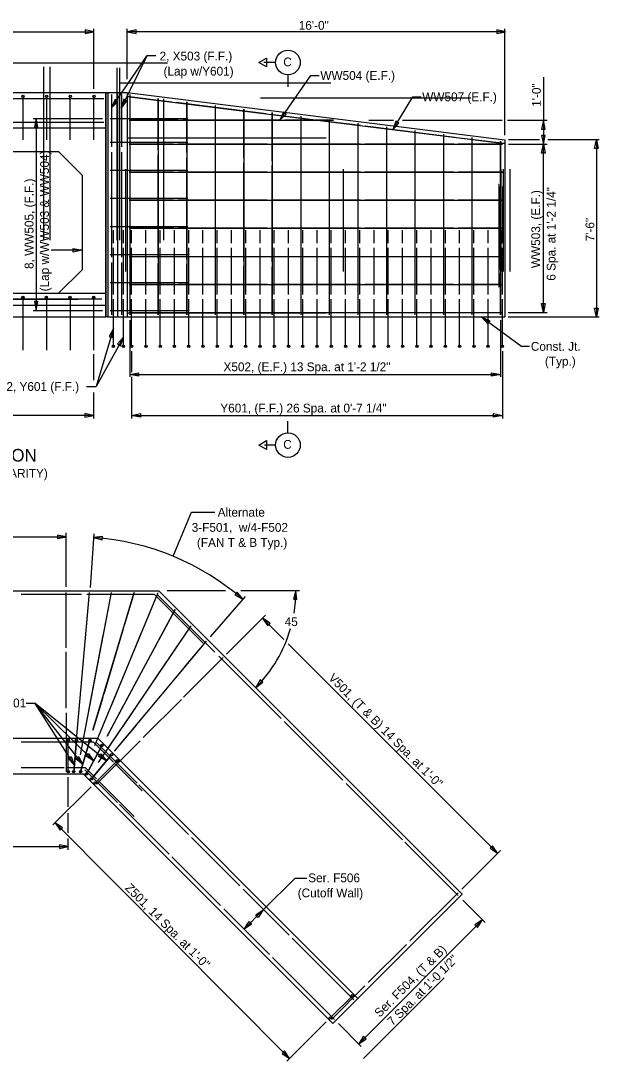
# Model space of a CAD drawing. Extents: x -1609 to 1184, y -412 to 394.
# Drawn here: x 695.6 to 720.11, y 231.37 to 275.43 of the extents above; entities that cross this region are included whole.
import ezdxf

# ---------------------------------------------------------------- set-up
doc = ezdxf.new("R2010")
doc.units = 0
for name, color, linetype in [('DR_P_Culvert', 7, 'Continuous'), ('DR_P_Headwall', 7, 'Continuous'), ('GE_P_CL_10', 7, 'Continuous'), ('ST_Details', 7, 'Continuous'), ('ST_Text', 7, 'Continuous')]:
    doc.layers.add(name, color=color, linetype=linetype)

msp = doc.modelspace()

# ---------------------------------------------------------------- linework, layer by layer
at = {"layer": 'DR_P_Culvert'}
for p, q in [((692.897, 273.646), (701.812, 273.646)), ((699.817, 272.805), (708.733, 272.805)), ((685.284, 272.144), (699.117, 272.144)), ((695.7, 270.391), (695.7, 272.227)), ((696.7, 270.391), (696.7, 272.227)), ((697.7, 270.391), (697.7, 272.227)), ((698.7, 270.391), (698.7, 272.227)), ((705.758, 272.169), (714.674, 272.169)), ((685.284, 271.141), (699.117, 271.141)), ((685.2, 270.891), (699.2, 270.891)), ((699.2, 270.891), (699.2, 262.894)), ((687.2, 269.891), (697.2, 269.891)), ((697.2, 269.891), (698.2, 268.891)), ((698.2, 268.891), (698.2, 264.891)), ((697.2, 263.891), (698.2, 264.891)), ((686.367, 263.641), (698.034, 263.641)), ((699.034, 263.641), (695.256, 263.641)), ((695.69, 263.724), (695.69, 261.477)), ((695.69, 263.724), (695.69, 261.477)), ((696.69, 263.724), (696.69, 261.477)), ((696.69, 263.724), (696.69, 261.477)), ((697.69, 263.724), (697.69, 261.477)), ((697.69, 263.724), (697.69, 261.477)), ((698.69, 263.724), (698.69, 261.477)), ((698.69, 263.724), (698.69, 261.477)), ((685.2, 262.894), (699.2, 262.894))]:
    msp.add_line(p, q, dxfattribs=at)
msp.add_lwpolyline([(699.2, 272.394), (699.285, 272.394), (699.285, 262.894), (699.2, 262.894)], close=True, dxfattribs=at)
for points in [[(694.012, 272.144), (697.306, 272.144)], [(697.47, 272.144), (699.117, 272.144)], [(694.012, 271.141), (697.306, 271.141)], [(697.47, 271.141), (699.117, 271.141)]]:
    msp.add_lwpolyline(points, dxfattribs=at)
at = {"layer": 'DR_P_Headwall'}
for p, q in [((685.2, 272.394), (699.2, 272.394)), ((699.2, 272.394), (699.2, 270.891)), ((699.285, 272.394), (699.285, 262.894)), ((699.285, 272.394), (700.113, 272.394)), ((699.699, 272.394), (699.699, 262.894)), ((700.113, 272.394), (716.112, 270.394)), ((700.113, 272.394), (700.113, 262.894)), ((716.112, 270.394), (716.112, 262.894)), ((687.2, 263.891), (697.2, 263.891)), ((697.2, 263.891), (699.2, 263.891)), ((699.2, 263.891), (699.2, 262.894)), ((685.2, 263.394), (699.2, 263.394)), ((685.2, 262.894), (698.2, 262.894)), ((677.116, 251.299), (701.457, 251.299)), ((714.308, 238.448), (701.457, 251.299)), ((677.116, 245.049), (698.868, 245.049)), ((709.889, 234.028), (698.868, 245.049)), ((677.116, 243.549), (698.247, 243.549)), ((708.829, 232.968), (698.247, 243.549)), ((714.308, 238.448), (708.829, 232.968))]:
    msp.add_line(p, q, dxfattribs=at)
for points in [[(699.446, 272.31), (699.446, 270.088)], [(699.869, 272.31), (699.869, 270.088)], [(699.446, 269.866), (699.446, 265.421)], [(699.869, 269.866), (699.869, 265.421)], [(699.446, 265.199), (699.446, 262.977)], [(699.869, 265.199), (699.869, 262.977)]]:
    msp.add_lwpolyline(points, dxfattribs=at)
at = {"layer": 'ST_Details'}
for p, q in [((696.565, 273.477), (696.565, 266.144)), ((696.828, 273.477), (696.828, 266.144)), ((699.676, 273.443), (699.676, 266.144)), ((699.791, 273.443), (699.791, 266.144)), ((700.217, 272.31), (700.217, 262.977)), ((700.092, 272.228), (716.091, 270.228)), ((701.425, 272.146), (701.425, 262.977)), ((701.644, 272.119), (701.644, 266.144)), ((702.634, 271.995), (702.634, 262.977)), ((703.842, 271.844), (703.842, 262.977)), ((705.05, 271.693), (705.05, 262.977)), ((706.259, 271.542), (706.259, 262.977)), ((707.467, 271.391), (707.467, 262.977)), ((699.388, 271.3), (702.685, 271.3)), ((700.196, 271.216), (708.859, 271.216)), ((708.675, 271.24), (708.675, 262.977)), ((709.884, 271.089), (709.884, 262.977)), ((711.092, 270.938), (711.092, 262.977)), ((712.3, 270.786), (712.3, 262.977)), ((713.509, 270.635), (713.509, 262.977)), ((699.388, 270.289), (702.685, 270.289)), ((700.123, 270.477), (708.539, 270.477)), ((700.196, 270.205), (716.019, 270.205)), ((714.717, 270.484), (714.717, 262.977)), ((715.925, 270.333), (715.925, 262.977)), ((699.388, 269.101), (702.685, 269.101)), ((700.043, 269.144), (700.043, 264.811)), ((700.196, 269.018), (716.019, 269.018)), ((709.262, 269.144), (709.262, 264.811)), ((715.936, 269.144), (715.936, 264.811)), ((716.036, 269.144), (716.036, 264.811)), ((716.316, 269.144), (716.316, 264.811)), ((715.853, 268.531), (715.853, 264.144)), ((716.009, 268.413), (716.009, 266.443)), ((699.388, 267.914), (702.685, 267.914)), ((700.196, 267.83), (716.019, 267.83)), ((699.388, 266.726), (702.685, 266.726)), ((699.529, 266.011), (699.529, 266.561)), ((699.952, 266.011), (699.952, 266.561)), ((700.196, 266.643), (716.019, 266.643)), ((700.3, 266.01), (700.3, 266.561)), ((700.904, 266.01), (700.904, 266.561)), ((701.509, 266.01), (701.509, 266.561)), ((702.113, 266.01), (702.113, 266.561)), ((702.717, 266.01), (702.717, 266.561)), ((703.321, 266.01), (703.321, 266.561)), ((703.925, 266.01), (703.925, 266.561)), ((704.529, 266.01), (704.529, 266.561)), ((705.134, 266.01), (705.134, 266.561)), ((705.738, 266.01), (705.738, 266.561)), ((706.342, 266.01), (706.342, 266.561)), ((706.946, 266.01), (706.946, 266.561)), ((707.55, 266.01), (707.55, 266.561)), ((708.154, 266.01), (708.154, 266.561)), ((708.759, 266.01), (708.759, 266.561)), ((709.363, 266.01), (709.363, 266.561)), ((709.967, 266.01), (709.967, 266.561)), ((710.571, 266.01), (710.571, 266.561)), ((711.175, 266.01), (711.175, 266.561)), ((711.779, 266.01), (711.779, 266.561)), ((712.384, 266.01), (712.384, 266.561)), ((712.988, 266.01), (712.988, 266.561)), ((713.592, 266.01), (713.592, 266.561)), ((714.196, 266.01), (714.196, 266.561)), ((714.8, 266.01), (714.8, 266.561)), ((715.404, 266.01), (715.404, 266.561)), ((716.009, 266.01), (716.009, 266.561)), ((699.529, 263.844), (699.529, 265.811)), ((699.952, 263.844), (699.952, 265.811)), ((700.3, 263.844), (700.3, 265.81)), ((700.904, 263.844), (700.904, 265.81)), ((701.509, 263.844), (701.509, 265.81)), ((702.113, 263.844), (702.113, 265.81)), ((702.717, 263.844), (702.717, 265.81)), ((703.321, 263.844), (703.321, 265.81)), ((703.925, 263.844), (703.925, 265.81)), ((704.529, 263.844), (704.529, 265.81)), ((705.134, 263.844), (705.134, 265.81)), ((705.738, 263.844), (705.738, 265.81)), ((706.342, 263.844), (706.342, 265.81)), ((706.946, 263.844), (706.946, 265.81)), ((707.55, 263.844), (707.55, 265.81)), ((708.154, 263.844), (708.154, 265.81)), ((708.759, 263.844), (708.759, 265.81)), ((709.363, 263.844), (709.363, 265.81)), ((709.967, 263.844), (709.967, 265.81)), ((710.571, 263.844), (710.571, 265.81)), ((711.175, 263.844), (711.175, 265.81)), ((711.779, 263.844), (711.779, 265.81)), ((712.384, 263.844), (712.384, 265.81)), ((712.988, 263.844), (712.988, 265.81)), ((713.592, 263.844), (713.592, 265.81)), ((714.196, 263.844), (714.196, 265.81)), ((714.8, 263.844), (714.8, 265.81)), ((715.404, 263.844), (715.404, 265.81)), ((716.009, 263.844), (716.009, 265.81)), ((699.388, 265.539), (702.685, 265.539)), ((700.196, 265.455), (716.019, 265.455)), ((699.388, 264.351), (702.685, 264.351)), ((700.196, 264.268), (716.019, 264.268)), ((699.388, 263.164), (702.685, 263.164)), ((700.123, 263.06), (708.539, 263.06)), ((700.196, 263.08), (716.019, 263.08)), ((699.285, 262.894), (716.112, 262.894)), ((697.532, 248.876), (697.532, 251.216)), ((701.27, 251.132), (698.396, 251.132)), ((703.332, 249.07), (701.27, 251.132)), ((703.827, 248.693), (701.388, 251.132)), ((697.532, 246.327), (697.532, 248.716)), ((706.639, 245.881), (703.989, 248.531)), ((702.502, 246.792), (704.174, 248.464)), ((700.789, 245.079), (702.406, 246.697)), ((697.532, 246.13), (697.532, 243.633)), ((709.25, 243.27), (706.763, 245.758)), ((698.812, 243.102), (700.657, 244.947)), ((697.438, 244.883), (695.616, 244.883)), ((698.681, 244.883), (697.558, 244.883)), ((698.681, 244.883), (699.524, 244.04)), ((698.799, 244.883), (700.532, 243.15)), ((699.696, 244.104), (698.753, 243.161)), ((697.438, 243.8), (695.616, 243.8)), ((698.35, 243.8), (697.558, 243.8)), ((699.707, 242.325), (698.316, 243.716)), ((698.817, 243.333), (698.35, 243.8)), ((699.609, 243.955), (700.744, 242.821)), ((700.413, 241.737), (698.902, 243.248)), ((700.606, 243.076), (702.709, 240.973)), ((701.884, 240.148), (699.781, 242.251)), ((702.832, 240.85), (704.885, 238.797)), ((704.06, 237.972), (702.007, 240.025)), ((705.026, 238.656), (706.975, 236.707)), ((712.093, 236.468), (714.132, 238.507)), ((710.325, 234.7), (711.941, 236.316)), ((713.536, 234.905), (710.118, 231.487)), ((708.77, 233.145), (710.184, 234.559)), ((709.654, 234.146), (708.711, 233.204))]:
    msp.add_line(p, q, dxfattribs=at)
for points in [[(700.217, 272.31), (700.217, 270.088)], [(701.997, 271.99), (700.092, 272.228)], [(701.425, 269.963), (701.425, 272.146)], [(705.997, 271.49), (702.187, 271.966)], [(702.634, 269.848), (702.634, 271.995)], [(703.842, 271.844), (703.842, 269.733)], [(705.05, 269.617), (705.05, 271.693)], [(708.092, 271.228), (706.187, 271.466)], [(706.259, 269.502), (706.259, 271.542)], [(707.467, 271.391), (707.467, 269.387)], [(702.259, 271.216), (700.196, 271.216)], [(706.59, 271.216), (702.465, 271.216)], [(708.859, 271.216), (706.797, 271.216)], [(709.997, 270.99), (708.092, 271.228)], [(708.675, 271.239), (708.675, 269.272)], [(709.884, 271.088), (709.884, 269.157)], [(713.996, 270.49), (710.187, 270.966)], [(711.092, 270.937), (711.092, 269.042)], [(712.3, 270.786), (712.3, 268.927)], [(713.509, 270.635), (713.509, 268.812)], [(702.08, 270.205), (700.196, 270.205)], [(706.035, 270.205), (702.268, 270.205)], [(708.107, 270.205), (706.224, 270.205)], [(709.991, 270.205), (708.108, 270.205)], [(713.947, 270.205), (710.18, 270.205)], [(716.019, 270.205), (714.135, 270.205)], [(716.091, 270.228), (714.187, 270.466)], [(714.717, 270.484), (714.717, 268.697)], [(715.925, 268.582), (715.925, 270.333)], [(700.217, 269.866), (700.217, 265.421)], [(701.425, 265.378), (701.425, 269.744)], [(702.634, 265.339), (702.634, 269.633)], [(703.842, 269.521), (703.842, 265.299)], [(705.05, 265.26), (705.05, 269.41)], [(706.259, 265.22), (706.259, 269.298)], [(707.467, 269.187), (707.467, 265.181)], [(702.08, 269.018), (700.196, 269.018)], [(706.035, 269.018), (702.268, 269.018)], [(708.107, 269.018), (706.224, 269.018)], [(709.991, 269.018), (708.108, 269.018)], [(708.675, 269.075), (708.675, 265.141)], [(709.884, 268.964), (709.884, 265.101)], [(713.947, 269.018), (710.18, 269.018)], [(711.092, 268.853), (711.092, 265.062)], [(712.3, 268.741), (712.3, 265.022)], [(716.019, 269.018), (714.135, 269.018)], [(713.509, 268.63), (713.509, 264.983)], [(714.717, 268.518), (714.717, 264.943)], [(715.925, 264.904), (715.925, 268.407)], [(702.08, 267.83), (700.196, 267.83)], [(706.035, 267.83), (702.268, 267.83)], [(708.107, 267.83), (706.224, 267.83)], [(709.991, 267.83), (708.108, 267.83)], [(713.947, 267.83), (710.18, 267.83)], [(716.019, 267.83), (714.135, 267.83)], [(702.08, 266.643), (700.196, 266.643)], [(706.035, 266.643), (702.268, 266.643)], [(708.107, 266.643), (706.224, 266.643)], [(709.991, 266.643), (708.108, 266.643)], [(713.947, 266.643), (710.18, 266.643)], [(716.019, 266.643), (714.135, 266.643)], [(700.196, 265.455), (702.08, 265.455)], [(702.268, 265.455), (706.035, 265.455)], [(706.224, 265.455), (708.107, 265.455)], [(708.108, 265.455), (709.991, 265.455)], [(710.18, 265.455), (713.947, 265.455)], [(714.135, 265.455), (716.019, 265.455)], [(700.217, 265.199), (700.217, 262.977)], [(701.425, 262.977), (701.425, 265.16)], [(702.634, 262.977), (702.634, 265.124)], [(703.842, 265.088), (703.842, 262.977)], [(705.05, 262.977), (705.05, 265.052)], [(706.259, 262.977), (706.259, 265.016)], [(707.467, 264.98), (707.467, 262.977)], [(708.675, 264.944), (708.675, 262.977)], [(709.884, 264.908), (709.884, 262.977)], [(711.092, 264.872), (711.092, 262.977)], [(712.3, 264.836), (712.3, 262.977)], [(713.509, 264.8), (713.509, 262.977)], [(714.717, 264.764), (714.717, 262.977)], [(715.925, 262.977), (715.925, 264.728)], [(702.08, 264.268), (700.196, 264.268)], [(706.035, 264.268), (702.268, 264.268)], [(708.107, 264.268), (706.224, 264.268)], [(709.991, 264.268), (708.108, 264.268)], [(713.947, 264.268), (710.18, 264.268)], [(716.019, 264.268), (714.135, 264.268)], [(699.529, 261.644), (699.529, 263.644)], [(699.952, 261.644), (699.952, 263.644)], [(700.3, 261.644), (700.3, 263.644)], [(700.904, 261.644), (700.904, 263.644)], [(701.509, 261.644), (701.509, 263.644)], [(702.113, 261.644), (702.113, 263.644)], [(702.717, 261.644), (702.717, 263.644)], [(703.321, 261.644), (703.321, 263.644)], [(703.925, 261.644), (703.925, 263.644)], [(704.529, 261.644), (704.529, 263.644)], [(705.134, 261.644), (705.134, 263.644)], [(705.738, 261.644), (705.738, 263.644)], [(706.342, 261.644), (706.342, 263.644)], [(706.946, 261.644), (706.946, 263.644)], [(707.55, 261.644), (707.55, 263.644)], [(708.154, 261.644), (708.154, 263.644)], [(708.759, 261.644), (708.759, 263.644)], [(709.363, 261.644), (709.363, 263.644)], [(709.967, 261.644), (709.967, 263.644)], [(710.571, 261.644), (710.571, 263.644)], [(711.175, 261.644), (711.175, 263.644)], [(711.779, 261.644), (711.779, 263.644)], [(712.384, 261.644), (712.384, 263.644)], [(712.988, 261.644), (712.988, 263.644)], [(713.592, 261.644), (713.592, 263.644)], [(714.196, 261.644), (714.196, 263.644)], [(714.8, 261.644), (714.8, 263.644)], [(715.404, 261.644), (715.404, 263.644)], [(716.009, 261.644), (716.009, 263.644)], [(700.196, 263.08), (702.08, 263.08)], [(702.268, 263.08), (706.035, 263.08)], [(706.224, 263.08), (708.107, 263.08)], [(708.108, 263.08), (709.991, 263.08)], [(710.18, 263.08), (713.947, 263.08)], [(714.135, 263.08), (716.019, 263.08)], [(698.178, 251.132), (695.616, 251.132)], [(697.615, 243.633), (697.615, 244.966)], [(711.773, 240.747), (709.392, 243.128)], [(711.877, 240.643), (714.132, 238.388)], [(706.146, 235.886), (704.201, 237.831)], [(707.094, 236.588), (709.713, 233.969)], [(708.888, 233.144), (706.265, 235.767)], [(709.653, 234.146), (708.711, 233.204)]]:
    msp.add_lwpolyline(points, dxfattribs=at)
msp.add_lwpolyline([(705.684, 257.464), (706.008, 257.651), (706.008, 257.277)], close=True, dxfattribs=at)
for centre in [(695.7, 272.227), (696.7, 272.227), (697.7, 272.227), (698.7, 272.227), (695.69, 263.724), (696.69, 263.724), (697.69, 263.724), (698.69, 263.724), (699.529, 261.644), (699.952, 261.644), (700.3, 261.643), (700.904, 261.643), (701.509, 261.643), (702.113, 261.643), (702.717, 261.643), (703.321, 261.643), (703.925, 261.643), (704.529, 261.643), (705.134, 261.643), (705.738, 261.643), (706.342, 261.643), (706.946, 261.643), (707.55, 261.643), (708.154, 261.643), (708.759, 261.643), (709.363, 261.643), (709.967, 261.643), (710.571, 261.643), (711.175, 261.643), (711.779, 261.643), (712.384, 261.643), (712.988, 261.643), (713.592, 261.643), (714.196, 261.643), (714.8, 261.643), (715.404, 261.643), (716.009, 261.643), (697.615, 244.966), (697.963, 244.966), (698.534, 244.966), (699.046, 244.754), (699.45, 244.35), (699.696, 244.104), (697.615, 243.633), (697.844, 243.633), (698.136, 243.633), (698.385, 243.53), (698.591, 243.323), (698.753, 243.161), (709.654, 234.146), (708.711, 233.204)]:
    msp.add_circle(centre, 0.0502, dxfattribs=at)
at = {"layer": 'ST_Text'}
for p, q in [((685.7, 274.966), (698.7, 274.966)), ((698.7, 272.552), (698.7, 275.085)), ((700.113, 272.962), (700.113, 275.085)), ((716.142, 274.966), (700.113, 274.966)), ((716.112, 270.581), (716.112, 275.085)), ((699.446, 271.75), (700.964, 273.957)), ((699.869, 271.741), (700.964, 273.957)), ((700.964, 273.957), (701.322, 273.957)), ((706.4, 273.665), (705.905, 273.665)), ((706.922, 273.143), (706.922, 272.628)), ((706.577, 271.216), (707.885, 273.116)), ((707.885, 273.116), (708.243, 273.116)), ((717.746, 273.042), (717.746, 271.216)), ((711.37, 270.818), (712.21, 272.216)), ((712.21, 272.216), (712.567, 272.216)), ((696.121, 271.3), (699.067, 271.3)), ((696.252, 271.3), (696.252, 263.164)), ((710.353, 271.216), (711.395, 271.216)), ((711.777, 271.216), (715.993, 271.216)), ((716.228, 271.216), (717.909, 271.216)), ((717.746, 271.216), (717.746, 270.205)), ((717.573, 270.394), (716.271, 270.394)), ((716.271, 270.205), (717.909, 270.205)), ((717.746, 263.08), (717.746, 270.205)), ((720.109, 270.394), (717.929, 270.394)), ((719.99, 270.394), (719.99, 262.894)), ((698.2, 265.711), (696.891, 265.711)), ((696.121, 263.164), (699.067, 263.164)), ((716.252, 263.08), (717.909, 263.08)), ((700.217, 262.754), (700.217, 260.351)), ((715.126, 262.894), (716.838, 261.643)), ((715.926, 262.758), (715.926, 260.351)), ((716.252, 262.894), (720.109, 262.894)), ((699.529, 262.403), (698.793, 259.945)), ((699.952, 262.033), (698.793, 259.945)), ((698.69, 261.307), (698.69, 260.215)), ((700.3, 261.447), (700.3, 260.548)), ((716.009, 261.447), (716.009, 258.584)), ((717.159, 261.643), (716.838, 261.643)), ((700.217, 260.453), (715.926, 260.453)), ((698.394, 259.945), (698.793, 259.945)), ((700.3, 260.351), (700.3, 258.584)), ((698.69, 259.693), (698.69, 258.584)), ((698.69, 258.721), (685.69, 258.721)), ((700.3, 258.721), (716.009, 258.721)), ((706.922, 257.986), (706.922, 258.476)), ((706.4, 257.464), (705.934, 257.464)), ((702.06, 252.754), (702.837, 254.63)), ((702.837, 254.63), (703.828, 254.63)), ((677.283, 253.581), (697.531, 253.581)), ((697.531, 251.465), (697.531, 253.752)), ((698.701, 253.712), (698.536, 251.429)), ((697.98, 245.156), (698.52, 251.216)), ((698.126, 244.341), (699.443, 251.216)), ((698.661, 245.391), (700.403, 251.216)), ((698.744, 244.748), (701.423, 251.216)), ((704.27, 251.299), (701.803, 251.299)), ((707.418, 251.299), (704.919, 251.299)), ((705.112, 251.057), (703.631, 249.344)), ((699.256, 245.144), (702.143, 250.495)), ((704.318, 248.609), (705.97, 250.261)), ((698.893, 244.023), (702.822, 249.816)), ((706.754, 249.229), (705.846, 250.137)), ((699.574, 244.499), (703.475, 249.163)), ((715.804, 240.179), (706.929, 249.054)), ((696.207, 246.516), (695.833, 246.516)), ((698.686, 244.089), (696.207, 246.516)), ((699.235, 244.093), (696.207, 246.516)), ((697.87, 243.921), (696.207, 246.516)), ((698.225, 243.932), (696.207, 246.516)), ((697.844, 243.633), (697.963, 244.966)), ((698.136, 243.633), (698.534, 244.966)), ((698.385, 243.53), (699.046, 244.754)), ((698.591, 243.323), (699.45, 244.35)), ((697.615, 242.143), (697.615, 243.401)), ((698.591, 242.994), (696.966, 241.378)), ((697.615, 241.046), (697.615, 241.88)), ((706.988, 231.489), (697.059, 241.47)), ((697.615, 240.322), (697.615, 240.803)), ((677.366, 240.464), (697.615, 240.464)), ((714.285, 238.66), (715.928, 240.303)), ((707.212, 239.116), (705.875, 237.779)), ((707.716, 239.116), (707.212, 239.116)), ((714.329, 238.191), (715.274, 237.246)), ((705.875, 237.779), (705.064, 236.968)), ((715.163, 237.357), (709.919, 232.113)), ((708.542, 233.035), (706.873, 231.375)), ((709.065, 232.967), (710.03, 232.002))]:
    msp.add_line(p, q, dxfattribs=at)
for points in [[(698.327, 274.891), (698.7, 274.966), (698.327, 275.041)], [(700.486, 275.041), (700.113, 274.966), (700.486, 274.891)], [(715.769, 274.891), (716.142, 274.966), (715.769, 275.041)], [(705.684, 273.665), (706.008, 273.852), (706.008, 273.478)], [(699.596, 272.1), (699.446, 271.75), (699.719, 272.016)], [(699.967, 272.109), (699.869, 271.741), (700.101, 272.043)], [(706.728, 271.566), (706.577, 271.216), (706.851, 271.481)], [(696.327, 270.926), (696.252, 271.3), (696.177, 270.926)], [(711.498, 271.177), (711.37, 270.818), (711.626, 271.101)], [(717.82, 270.843), (717.746, 271.216), (717.671, 270.843)], [(717.671, 270.579), (717.746, 270.205), (717.82, 270.579)], [(717.671, 269.832), (717.746, 270.205), (717.82, 269.832)], [(719.915, 270.02), (719.99, 270.394), (720.064, 270.02)], [(697.827, 265.785), (698.2, 265.711), (697.827, 265.636)], [(696.177, 263.537), (696.252, 263.164), (696.327, 263.537)], [(717.82, 263.454), (717.746, 263.08), (717.671, 263.454)], [(720.064, 263.267), (719.99, 262.894), (719.915, 263.267)], [(715.382, 262.611), (715.126, 262.894), (715.471, 262.731)], [(699.493, 262.024), (699.529, 262.403), (699.35, 262.067)], [(699.831, 261.672), (699.952, 262.033), (699.702, 261.746)], [(700.59, 260.378), (700.217, 260.453), (700.59, 260.528)], [(715.552, 260.528), (715.926, 260.453), (715.552, 260.378)], [(698.316, 258.646), (698.69, 258.721), (698.316, 258.795)], [(700.674, 258.646), (700.3, 258.721), (700.674, 258.795)], [(715.635, 258.795), (716.009, 258.721), (715.635, 258.646)], [(697.158, 253.506), (697.531, 253.581), (697.158, 253.655)], [(699.068, 253.596), (698.69, 253.553), (699.056, 253.448)], [(704.673, 251.118), (705.007, 250.936), (704.768, 251.232)], [(707.301, 250.921), (707.258, 251.299), (707.152, 250.933)], [(706.163, 249.926), (705.846, 250.137), (706.057, 249.82)], [(705.746, 247.529), (705.559, 247.197), (705.859, 247.431)], [(697.731, 244.275), (697.87, 243.921), (697.605, 244.194)], [(698.055, 244.273), (698.225, 243.932), (697.937, 244.181)], [(698.47, 244.402), (698.686, 244.089), (698.366, 244.295)], [(698.993, 244.387), (699.235, 244.093), (698.898, 244.271)], [(697.375, 241.258), (697.059, 241.47), (697.269, 241.153)], [(697.242, 240.387), (697.615, 240.464), (697.241, 240.536)], [(715.487, 240.39), (715.804, 240.179), (715.593, 240.496)], [(705.558, 237.568), (705.875, 237.779), (705.664, 237.462)], [(705.381, 237.179), (705.064, 236.968), (705.275, 237.285)], [(714.952, 237.04), (715.163, 237.357), (714.846, 237.146)], [(710.13, 232.43), (709.919, 232.113), (710.236, 232.324)], [(706.672, 231.701), (706.988, 231.489), (706.778, 231.807)]]:
    msp.add_lwpolyline(points, close=True, dxfattribs=at)
for points in [[(698.392, 249.773), (698.52, 251.216)], [(699.13, 249.579), (699.443, 251.215)], [(700.403, 251.216), (699.989, 249.829)], [(700.785, 249.676), (701.422, 251.216)], [(702.143, 250.495), (701.456, 249.221)], [(701.886, 248.437), (702.822, 249.816)], [(698.121, 246.743), (698.379, 249.629)], [(698.471, 246.141), (699.098, 249.415)], [(699.947, 249.69), (699.118, 246.916)], [(699.445, 246.442), (700.721, 249.522)], [(701.387, 249.094), (700.012, 246.546)], [(702.546, 248.053), (703.475, 249.163)], [(699.922, 245.54), (701.793, 248.299)], [(700.596, 245.721), (702.453, 247.942)], [(699.076, 246.778), (698.661, 245.391)], [(697.98, 245.157), (698.108, 246.599)], [(698.744, 244.749), (699.382, 246.288)], [(699.943, 246.418), (699.256, 245.144)], [(698.126, 244.341), (698.439, 245.978)], [(698.893, 244.023), (699.828, 245.402)], [(699.575, 244.499), (700.503, 245.61)], [(697.963, 244.966), (697.844, 243.633)], [(698.534, 244.966), (698.136, 243.633)], [(699.046, 244.754), (698.385, 243.53)], [(699.45, 244.35), (698.591, 243.323)]]:
    msp.add_lwpolyline(points, dxfattribs=at)
for centre in [(706.922, 273.665), (706.922, 257.464)]:
    msp.add_circle(centre, 0.522, dxfattribs=at)
for centre, radius, start, end in [((697.904, 242.721), 10.86, 49.1506, 85.8508), ((701.457, 251.299), 5.801, 350.5465, 360), ((701.457, 251.299), 5.801, 315, 344.0165)]:
    msp.add_arc(centre, radius, start, end, dxfattribs=at)

# ---------------------------------------------------------------- texts
at = {"layer": 'GE_P_CL_10'}
msp.add_text('45', height=0.3733, dxfattribs=at).set_placement((706.784, 249.8))
at = {"layer": 'ST_Text'}
for s, height, p in [('16\'-0"', 0.3733, (707.379, 275.051)), ('2, X503 (F.F.)', 0.37335, (701.483, 273.75)), ('C', 0.373, (706.723, 273.501)), ('(Lap w/Y601)', 0.37335, (701.651, 273.11)), ('WW504 (E.F.)', 0.37335, (708.295, 272.929)), ('WW507 (E.F.)', 0.37335, (712.611, 272.023)), ('Const. Jt.', 0.3733, (717.214, 261.457)), ('X502, (E.F.) 13 Spa. at 1\'-2 1/2"', 0.37335, (704.192, 260.592)), ('(Typ.)', 0.3733, (717.811, 260.829)), ('2, Y601 (F.F.)', 0.37335, (694.994, 259.757)), ('Y601, (F.F.) 26 Spa. at 0\'-7 1/4"', 0.37335, (704.057, 258.845)), ('OUTLET WINGWALL ELEVATION', 0.53335, (685.178, 256.767)), ('C', 0.373, (706.723, 257.307)), ('(FOOTING NOT SHOWN FOR CLARITY)', 0.37335, (687.456, 256.083)), ('Alternate', 0.3733, (703.946, 254.432)), ('3-F501,  w/4-F502', 0.37335, (702.845, 253.792)), ('(FAN T & B Typ.)', 0.37335, (703.066, 253.152)), ('Z501', 0.3733, (694.694, 246.357))]:
    msp.add_text(s, height=height, dxfattribs=at).set_placement(p)
for s, height, rotation, p in [('1\'-0"', 0.3733, 90, (717.635, 271.788)), ('(Lap w/WW503 & WW504)', 0.37335, 90, (696.795, 263.973)), ('8, WW505, (F.F.)', 0.37335, 90, (696.142, 264.921)), ('6 Spa. at 1\'-2 1/4"', 0.37335, 90, (718.259, 264.424)), ('WW503, (E.F.)', 0.37335, 90, (717.606, 264.958)), ('7\'-6"', 0.3733, 90, (719.904, 266.09)), ('V501, (T & B) 14 Spa. at 1\'-0"', 0.37335, 315, (708.607, 247.571)), ('Ser. F506', 0.3733, 360, (707.782, 238.953)), ('Z501, 14 Spa. at 1\'-0"', 0.37334, 314.8519, (699.993, 238.68)), ('(Cutoff Wall)', 0.37335, 360, (707.334, 238.313)), ('Ser. F504, (T & B)', 0.37334, 45, (710.808, 233.206)), ('7 Spa. at 1\'-0 1/2"', 0.37334, 45, (711.355, 232.848))]:
    msp.add_text(s, height=height, rotation=rotation, dxfattribs=at).set_placement(p)

doc.saveas('drawing.dxf')
